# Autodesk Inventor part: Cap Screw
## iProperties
Created: 2002-02
Part Number: Cap Screw
Document SubType Name: Modeling
Designer: ***
Control State: 0
Master: False
Checked Out: False
Shininess: 77.0
Length Units: 11269
Angle Units: 11279
Time Units: 11290
Mass Units: 11283
Length Display Precision: 3
Angle Display Precision: 2
Density: 0.0
Volumn: 0.0
Area: 0.0
PropertySet Name: Model Information
Author: ***
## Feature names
1. Revolution1
2. Extrusion1
3. Extrusion2
